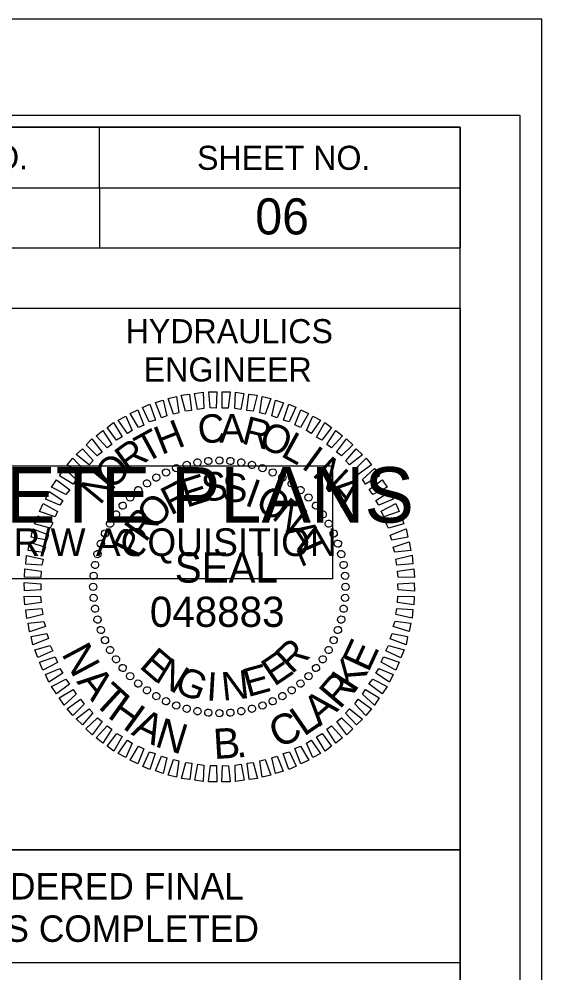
# Model space of a CAD drawing. Extents: x 1639431 to 1641888, y 841916 to 843940.
# Drawn here: x 1641779.1 to 1641887.8, y 842813.2 to 843011.3 of the extents above; entities that cross this region are included whole.
import ezdxf

# ---------------------------------------------------------------- set-up
doc = ezdxf.new("R2010")
doc.units = 0
for name, color, linetype in [('Default', 7, 'Continuous'), ('Old_Level_2', 7, 'Continuous'), ('Sheet Data Field CELL', 7, 'Continuous'), ('Sheet Plan CELL', 7, 'Continuous'), ('Sheet Plot Border Inside CELL', 7, 'Continuous'), ('Sheet Plot Border Outside CELL', 7, 'Continuous'), ('Sheet Sticker Exception Certification CELL', 7, 'Continuous'), ('Sheet Sticker Incomplete CELL', 7, 'Continuous')]:
    doc.layers.add(name, color=color, linetype=linetype)

msp = doc.modelspace()

# ---------------------------------------------------------------- linework, layer by layer
at = {"layer": 'Old_Level_2'}
for p, q in [((1641813.93, 842918.72), (1641813.93, 842918.72)), ((1641816.22, 842919.18), (1641816.22, 842919.18)), ((1641818.46, 842919.53), (1641818.46, 842919.53)), ((1641820.76, 842919.62), (1641820.76, 842919.62)), ((1641823.07, 842919.51), (1641823.07, 842919.51)), ((1641825.32, 842919.18), (1641825.32, 842919.18)), ((1641827.52, 842918.75), (1641827.52, 842918.75)), ((1641809.67, 842917.18), (1641809.67, 842917.18)), ((1641811.74, 842918.05), (1641811.74, 842918.05)), ((1641829.73, 842918.05), (1641829.73, 842918.05)), ((1641831.84, 842917.15), (1641831.84, 842917.15)), ((1641805.68, 842914.86), (1641805.68, 842914.86)), ((1641807.65, 842916.1), (1641807.65, 842916.1)), ((1641833.9, 842916.14), (1641833.9, 842916.14)), ((1641835.8, 842914.87), (1641835.8, 842914.87)), ((1641803.87, 842913.52), (1641803.87, 842913.52)), ((1641837.66, 842913.49), (1641837.66, 842913.49)), ((1641800.64, 842910.28), (1641800.64, 842910.28)), ((1641802.18, 842911.92), (1641802.18, 842911.92)), ((1641839.31, 842911.95), (1641839.31, 842911.95)), ((1641840.9, 842910.25), (1641840.9, 842910.25)), ((1641799.26, 842908.42), (1641799.26, 842908.42)), ((1641842.24, 842908.44), (1641842.24, 842908.44)), ((1641797.98, 842906.52), (1641797.98, 842906.52)), ((1641843.48, 842906.47), (1641843.48, 842906.47)), ((1641796.97, 842904.46), (1641796.97, 842904.46)), ((1641844.56, 842904.45), (1641844.56, 842904.45)), ((1641796.07, 842902.35), (1641796.07, 842902.35)), ((1641845.43, 842902.38), (1641845.43, 842902.38)), ((1641795.37, 842900.14), (1641795.37, 842900.14)), ((1641846.1, 842900.19), (1641846.1, 842900.19)), ((1641794.94, 842897.94), (1641794.94, 842897.94)), ((1641846.56, 842897.9), (1641846.56, 842897.9)), ((1641794.61, 842895.69), (1641794.61, 842895.69)), ((1641846.91, 842895.66), (1641846.91, 842895.66)), ((1641794.5, 842893.38), (1641794.5, 842893.38)), ((1641820.75, 842893.37), (1641820.75, 842893.37)), ((1641847, 842893.36), (1641847, 842893.36)), ((1641794.59, 842891.08), (1641794.59, 842891.08)), ((1641846.89, 842891.05), (1641846.89, 842891.05)), ((1641794.94, 842888.84), (1641794.94, 842888.84)), ((1641846.56, 842888.8), (1641846.56, 842888.8)), ((1641795.4, 842886.55), (1641795.4, 842886.55)), ((1641846.13, 842886.6), (1641846.13, 842886.6)), ((1641796.07, 842884.36), (1641796.07, 842884.36)), ((1641845.43, 842884.39), (1641845.43, 842884.39)), ((1641796.94, 842882.29), (1641796.94, 842882.29)), ((1641844.53, 842882.28), (1641844.53, 842882.28)), ((1641798.02, 842880.27), (1641798.02, 842880.27)), ((1641843.52, 842880.22), (1641843.52, 842880.22)), ((1641799.26, 842878.3), (1641799.26, 842878.3)), ((1641842.25, 842878.32), (1641842.25, 842878.32)), ((1641800.6, 842876.49), (1641800.6, 842876.49)), ((1641802.2, 842874.79), (1641802.2, 842874.79)), ((1641839.33, 842874.82), (1641839.33, 842874.82)), ((1641840.87, 842876.46), (1641840.87, 842876.46)), ((1641803.84, 842873.25), (1641803.84, 842873.25)), ((1641837.63, 842873.22), (1641837.63, 842873.22)), ((1641805.7, 842871.87), (1641805.7, 842871.87)), ((1641807.6, 842870.6), (1641807.6, 842870.6)), ((1641833.86, 842870.64), (1641833.86, 842870.64)), ((1641835.82, 842871.88), (1641835.82, 842871.88)), ((1641809.66, 842869.59), (1641809.66, 842869.59)), ((1641811.77, 842868.69), (1641811.77, 842868.69)), ((1641829.76, 842868.69), (1641829.76, 842868.69)), ((1641831.83, 842869.56), (1641831.83, 842869.56)), ((1641813.98, 842867.99), (1641813.98, 842867.99)), ((1641816.18, 842867.56), (1641816.18, 842867.56)), ((1641818.44, 842867.23), (1641818.44, 842867.23)), ((1641820.74, 842867.12), (1641820.74, 842867.12)), ((1641823.04, 842867.21), (1641823.04, 842867.21)), ((1641825.28, 842867.56), (1641825.28, 842867.56)), ((1641827.57, 842868.02), (1641827.57, 842868.02))]:
    msp.add_line(p, q, dxfattribs=at)
for points in [[(1641808.74, 842928.51), (1641807.48, 842931.63), (1641809.09, 842932.13), (1641809.83, 842928.9)], [(1641811.23, 842929.24), (1641810.08, 842932.51), (1641811.85, 842932.91), (1641812.33, 842929.52)], [(1641813.73, 842929.85), (1641812.84, 842933.19), (1641814.56, 842933.37), (1641814.99, 842930.03)], [(1641816.24, 842930.21), (1641815.6, 842933.55), (1641817.38, 842933.79), (1641817.49, 842930.39)], [(1641818.85, 842930.52), (1641818.53, 842933.91), (1641820.25, 842933.89), (1641820.1, 842930.49)], [(1641821.36, 842930.51), (1641821.3, 842933.91), (1641823.02, 842933.89), (1641822.61, 842930.48)], [(1641823.97, 842930.4), (1641824.12, 842933.8), (1641825.85, 842933.52), (1641825.23, 842930.21)], [(1641826.49, 842930.03), (1641826.9, 842933.38), (1641828.63, 842933.15), (1641827.75, 842929.89)], [(1641829.17, 842929.5), (1641829.63, 842932.9), (1641831.42, 842932.52), (1641830.27, 842929.25)], [(1641831.69, 842928.86), (1641832.42, 842932.12), (1641834.05, 842931.62), (1641832.79, 842928.51)], [(1641803.91, 842926.49), (1641802.18, 842929.39), (1641803.79, 842930.15), (1641805.05, 842926.98)], [(1641806.19, 842927.63), (1641804.78, 842930.64), (1641806.33, 842931.29), (1641807.49, 842927.97)], [(1641834.06, 842927.96), (1641835.2, 842931.28), (1641836.68, 842930.67), (1641835.27, 842927.62)], [(1641836.43, 842927.01), (1641837.68, 842930.12), (1641839.31, 842929.41), (1641837.59, 842926.45)], [(1641801.68, 842925.2), (1641799.7, 842927.99), (1641801.3, 842928.85), (1641802.66, 842925.84)], [(1641838.85, 842925.85), (1641840.21, 842928.85), (1641841.8, 842927.99), (1641839.86, 842925.24)], [(1641799.4, 842923.85), (1641797.42, 842926.48), (1641798.77, 842927.5), (1641800.54, 842924.5)], [(1641840.92, 842924.47), (1641842.69, 842927.54), (1641844.07, 842926.46), (1641842.08, 842923.86)], [(1641795.38, 842920.59), (1641793.04, 842922.85), (1641794.27, 842924.13), (1641796.36, 842921.34)], [(1641797.45, 842922.25), (1641795.15, 842924.72), (1641796.55, 842925.84), (1641798.43, 842922.95)], [(1641843.09, 842922.94), (1641844.97, 842925.85), (1641846.35, 842924.72), (1641844.09, 842922.23)], [(1641845.1, 842921.36), (1641847.2, 842924.11), (1641848.48, 842922.88), (1641846.11, 842920.59)], [(1641793.69, 842918.73), (1641790.99, 842920.83), (1641792.27, 842922.05), (1641794.51, 842919.58)], [(1641847.02, 842919.56), (1641849.22, 842922.05), (1641850.5, 842920.82), (1641847.82, 842918.74)], [(1641791.89, 842916.71), (1641789.14, 842918.7), (1641790.27, 842920.08), (1641792.61, 842917.67)], [(1641848.88, 842917.71), (1641851.24, 842920.1), (1641852.37, 842918.71), (1641849.63, 842916.68)], [(1641790.36, 842914.7), (1641787.51, 842916.43), (1641788.47, 842917.96), (1641791.02, 842915.7)], [(1641850.48, 842915.7), (1641853.01, 842917.94), (1641854.03, 842916.44), (1641851.13, 842914.71)], [(1641788.83, 842912.58), (1641785.87, 842914.1), (1641786.89, 842915.58), (1641789.65, 842913.54)], [(1641851.88, 842913.58), (1641854.62, 842915.61), (1641855.64, 842914.06), (1641852.63, 842912.54)], [(1641787.61, 842910.31), (1641784.61, 842911.57), (1641785.37, 842913.2), (1641788.22, 842911.32)], [(1641853.28, 842911.3), (1641856.18, 842913.18), (1641856.88, 842911.57), (1641853.92, 842910.32)], [(1641786.61, 842907.89), (1641783.35, 842909.03), (1641784.1, 842910.67), (1641787.11, 842909.05)], [(1641854.36, 842909.07), (1641857.42, 842910.69), (1641858.13, 842909.03), (1641854.91, 842907.93)], [(1641785.6, 842905.57), (1641782.35, 842906.45), (1641783, 842908.09), (1641786.16, 842906.68)], [(1641855.35, 842906.63), (1641858.51, 842908.04), (1641859.12, 842906.43), (1641855.89, 842905.54)], [(1641784.86, 842903.05), (1641781.61, 842903.67), (1641781.95, 842905.4), (1641785.26, 842904.15)], [(1641856.23, 842904.13), (1641859.55, 842905.4), (1641859.9, 842903.68), (1641856.61, 842903.04)], [(1641784.23, 842900.52), (1641780.98, 842900.89), (1641781.31, 842902.67), (1641784.63, 842901.63)], [(1641856.9, 842901.64), (1641860.18, 842902.69), (1641860.52, 842900.92), (1641857.23, 842900.54)], [(1641783.86, 842897.85), (1641780.5, 842898.11), (1641780.68, 842899.89), (1641784.1, 842899.11)], [(1641857.41, 842899.14), (1641860.8, 842899.93), (1641860.99, 842898.15), (1641857.65, 842897.88)], [(1641783.64, 842895.34), (1641780.24, 842895.38), (1641780.31, 842897.11), (1641783.72, 842896.59)], [(1641857.77, 842896.63), (1641861.16, 842897.11), (1641861.3, 842895.33), (1641857.9, 842895.38)], [(1641783.63, 842892.72), (1641780.24, 842892.51), (1641780.2, 842894.28), (1641783.61, 842893.98)], [(1641857.87, 842894.02), (1641861.27, 842894.23), (1641861.3, 842892.46), (1641857.89, 842892.76)], [(1641783.73, 842890.11), (1641780.34, 842889.63), (1641780.2, 842891.41), (1641783.6, 842891.36)], [(1641857.86, 842891.4), (1641861.26, 842891.36), (1641861.19, 842889.63), (1641857.78, 842890.15)], [(1641784.09, 842887.61), (1641780.7, 842886.81), (1641780.51, 842888.59), (1641783.86, 842888.86)], [(1641857.65, 842888.89), (1641861, 842888.63), (1641860.82, 842886.85), (1641857.41, 842887.63)], [(1641784.6, 842885.1), (1641781.32, 842884.05), (1641780.98, 842885.83), (1641784.27, 842886.2)], [(1641857.27, 842886.22), (1641860.52, 842885.85), (1641860.19, 842884.07), (1641856.87, 842885.11)], [(1641785.27, 842882.61), (1641781.95, 842881.34), (1641781.6, 842883.06), (1641784.89, 842883.7)], [(1641856.64, 842883.69), (1641859.89, 842883.07), (1641859.56, 842881.34), (1641856.24, 842882.59)], [(1641786.15, 842880.11), (1641782.99, 842878.7), (1641782.38, 842880.31), (1641785.61, 842881.2)], [(1641855.9, 842881.17), (1641859.16, 842880.29), (1641858.5, 842878.65), (1641855.34, 842880.06)], [(1641787.14, 842877.67), (1641784.08, 842876.05), (1641783.37, 842877.71), (1641786.59, 842878.81)], [(1641854.89, 842878.85), (1641858.15, 842877.71), (1641857.4, 842876.07), (1641854.39, 842877.69)], [(1641788.22, 842875.44), (1641785.33, 842873.56), (1641784.62, 842875.17), (1641787.58, 842876.42)], [(1641853.89, 842876.43), (1641856.89, 842875.17), (1641856.14, 842873.54), (1641853.28, 842875.42)], [(1641789.62, 842873.16), (1641786.88, 842871.13), (1641785.86, 842872.68), (1641788.87, 842874.2)], [(1641852.67, 842874.16), (1641855.63, 842872.64), (1641854.61, 842871.16), (1641851.85, 842873.2)], [(1641791.02, 842871.04), (1641788.49, 842868.8), (1641787.47, 842870.3), (1641790.37, 842872.03)], [(1641851.14, 842872.04), (1641854, 842870.31), (1641853.03, 842868.78), (1641850.48, 842871.04)], [(1641792.62, 842869.03), (1641790.26, 842866.64), (1641789.14, 842868.03), (1641791.87, 842870.06)], [(1641849.61, 842870.03), (1641852.36, 842868.04), (1641851.23, 842866.66), (1641848.89, 842869.07)], [(1641794.48, 842867.18), (1641792.28, 842864.69), (1641791, 842865.92), (1641793.69, 842868)], [(1641847.81, 842868.01), (1641850.52, 842865.91), (1641849.23, 842864.69), (1641846.99, 842867.16)], [(1641796.4, 842865.38), (1641794.3, 842862.63), (1641793.03, 842863.86), (1641795.39, 842866.15)], [(1641846.12, 842866.15), (1641848.46, 842863.89), (1641847.23, 842862.61), (1641845.14, 842865.4)], [(1641798.41, 842863.8), (1641796.53, 842860.89), (1641795.15, 842862.02), (1641797.41, 842864.51)], [(1641800.58, 842862.27), (1641798.81, 842859.2), (1641797.43, 842860.28), (1641799.42, 842862.88)], [(1641842.1, 842862.89), (1641844.08, 842860.26), (1641842.74, 842859.24), (1641840.96, 842862.24)], [(1641844.06, 842864.49), (1641846.35, 842862.02), (1641844.96, 842860.9), (1641843.07, 842863.79)], [(1641802.65, 842860.89), (1641801.29, 842857.89), (1641799.7, 842858.75), (1641801.64, 842861.5)], [(1641839.82, 842861.54), (1641841.8, 842858.75), (1641840.2, 842857.89), (1641838.84, 842860.9)], [(1641805.07, 842859.73), (1641803.82, 842856.62), (1641802.19, 842857.33), (1641803.91, 842860.29)], [(1641807.44, 842858.78), (1641806.3, 842855.46), (1641804.82, 842856.07), (1641806.23, 842859.12)], [(1641835.31, 842859.11), (1641836.72, 842856.1), (1641835.17, 842855.45), (1641834.01, 842858.77)], [(1641837.59, 842860.25), (1641839.32, 842857.35), (1641837.71, 842856.59), (1641836.45, 842859.76)], [(1641809.81, 842857.88), (1641809.08, 842854.62), (1641807.46, 842855.12), (1641808.71, 842858.23)], [(1641812.33, 842857.24), (1641811.87, 842853.84), (1641810.09, 842854.22), (1641811.23, 842857.49)], [(1641815.01, 842856.71), (1641814.6, 842853.36), (1641812.87, 842853.59), (1641813.75, 842856.85)], [(1641827.77, 842856.89), (1641828.66, 842853.55), (1641826.94, 842853.37), (1641826.52, 842856.71)], [(1641830.27, 842857.5), (1641831.42, 842854.23), (1641829.65, 842853.83), (1641829.17, 842857.22)], [(1641832.76, 842858.23), (1641834.02, 842855.11), (1641832.41, 842854.61), (1641831.67, 842857.84)], [(1641817.53, 842856.34), (1641817.38, 842852.94), (1641815.65, 842853.22), (1641816.27, 842856.53)], [(1641820.14, 842856.23), (1641820.2, 842852.83), (1641818.48, 842852.85), (1641818.89, 842856.26)], [(1641822.65, 842856.22), (1641822.97, 842852.83), (1641821.25, 842852.85), (1641821.4, 842856.25)], [(1641825.26, 842856.53), (1641825.9, 842853.19), (1641824.12, 842852.95), (1641824.01, 842856.35)]]:
    msp.add_lwpolyline(points, close=True, dxfattribs=at)
for centre, major_axis in [((1641818.46, 842919.5), (-0.066, 0.75)), ((1641820.75, 842919.6), (0, 0.753)), ((1641823.04, 842919.5), (0.066, 0.75)), ((1641811.78, 842918.02), (-0.258, 0.708)), ((1641813.96, 842918.7), (-0.195, 0.727)), ((1641816.2, 842919.2), (-0.131, 0.742)), ((1641825.3, 842919.2), (0.131, 0.742)), ((1641827.54, 842918.7), (0.195, 0.727)), ((1641829.72, 842918.02), (0.258, 0.708)), ((1641807.64, 842916.08), (-0.376, 0.652)), ((1641809.67, 842917.14), (-0.318, 0.682)), ((1641831.83, 842917.14), (0.318, 0.682)), ((1641833.86, 842916.08), (0.376, 0.652)), ((1641803.89, 842913.46), (-0.484, 0.577)), ((1641805.71, 842914.85), (-0.432, 0.617)), ((1641835.79, 842914.85), (0.432, 0.617)), ((1641837.61, 842913.46), (0.484, 0.577)), ((1641802.2, 842911.92), (-0.532, 0.532)), ((1641839.3, 842911.92), (0.532, 0.532)), ((1641800.66, 842910.23), (-0.577, 0.484)), ((1641840.84, 842910.23), (0.577, 0.484)), ((1641799.27, 842908.41), (-0.617, 0.432)), ((1641842.24, 842908.41), (0.617, 0.432)), ((1641798.04, 842906.48), (-0.652, 0.376)), ((1641843.46, 842906.48), (0.652, 0.376)), ((1641796.98, 842904.45), (-0.682, 0.318)), ((1641844.52, 842904.45), (0.682, 0.318)), ((1641796.1, 842902.34), (-0.708, 0.258)), ((1641845.4, 842902.34), (0.708, 0.258)), ((1641795.42, 842900.16), (-0.727, 0.195)), ((1641846.08, 842900.16), (0.727, 0.195)), ((1641794.92, 842897.92), (-0.742, 0.131)), ((1641846.58, 842897.92), (0.742, 0.131)), ((1641794.62, 842895.66), (-0.75, 0.066)), ((1641846.88, 842895.66), (0.75, 0.066)), ((1641794.52, 842893.37), (-0.753, 0)), ((1641846.98, 842893.37), (0.753, 0)), ((1641794.62, 842891.08), (-0.75, -0.066)), ((1641846.88, 842891.08), (0.75, -0.066)), ((1641794.92, 842888.82), (-0.742, -0.131)), ((1641846.58, 842888.82), (0.742, -0.131)), ((1641795.42, 842886.58), (-0.727, -0.195)), ((1641846.08, 842886.58), (0.727, -0.195)), ((1641796.1, 842884.4), (-0.708, -0.258)), ((1641845.4, 842884.4), (0.708, -0.258)), ((1641796.98, 842882.29), (-0.682, -0.318)), ((1641844.52, 842882.29), (0.682, -0.318)), ((1641798.04, 842880.26), (-0.652, -0.376)), ((1641843.46, 842880.26), (0.652, -0.376)), ((1641799.27, 842878.33), (-0.617, -0.432)), ((1641842.24, 842878.33), (0.617, -0.432)), ((1641800.66, 842876.51), (-0.577, -0.484)), ((1641840.84, 842876.51), (0.577, -0.484)), ((1641802.2, 842874.82), (-0.532, -0.532)), ((1641839.3, 842874.82), (0.532, -0.532)), ((1641803.89, 842873.28), (-0.484, -0.577)), ((1641805.71, 842871.89), (-0.432, -0.617)), ((1641835.79, 842871.89), (0.432, -0.617)), ((1641837.61, 842873.28), (0.484, -0.577)), ((1641807.64, 842870.66), (-0.376, -0.652)), ((1641833.86, 842870.66), (0.376, -0.652)), ((1641809.67, 842869.6), (-0.318, -0.682)), ((1641811.78, 842868.72), (-0.258, -0.708)), ((1641813.96, 842868.04), (-0.195, -0.727)), ((1641827.54, 842868.04), (0.195, -0.727)), ((1641829.72, 842868.72), (0.258, -0.708)), ((1641831.83, 842869.6), (0.318, -0.682)), ((1641816.2, 842867.54), (-0.131, -0.742)), ((1641818.46, 842867.24), (-0.066, -0.75)), ((1641820.75, 842867.14), (0, -0.753)), ((1641823.04, 842867.24), (0.066, -0.75)), ((1641825.3, 842867.54), (0.131, -0.742))]:
    msp.add_ellipse(centre, major_axis=major_axis, ratio=0.999708, dxfattribs=at)
at = {"layer": 'Sheet Plan CELL'}
for p, q in [((1641795.76, 842988.76), (1641795.81, 842963.76)), ((1641670.74, 842976.28), (1641870.79, 842976.27)), ((1641670.75, 842963.74), (1641870.79, 842963.77)), ((1641670.75, 842963.74), (1641870.79, 842963.77))]:
    msp.add_line(p, q, dxfattribs=at)
for points in [[(1640370.79, 841938.82), (1640370.76, 842988.79), (1641670.75, 842988.83), (1641670.76, 842838.77), (1641870.8, 842838.76), (1641870.8, 841938.82)], [(1641870.83, 842988.82), (1640370.79, 842988.82), (1640370.79, 841938.82), (1641870.8, 841938.82)], [(1641670.75, 842988.83), (1641870.83, 842988.82), (1641870.79, 842963.77), (1641670.75, 842963.74)], [(1641770.8, 842951.26), (1641870.79, 842951.27), (1641870.8, 842838.76), (1641770.8, 842838.74)]]:
    msp.add_lwpolyline(points, close=True, dxfattribs=at)
at = {"layer": 'Sheet Plot Border Inside CELL'}
msp.add_lwpolyline([(1640217.3, 841936.31), (1641883.29, 841936.32), (1641883.3, 842991.31), (1640217.3, 842991.31)], close=True, dxfattribs=at)
at = {"layer": 'Sheet Plot Border Outside CELL'}
msp.add_lwpolyline([(1640204.3, 841916.31), (1641887.8, 841916.31), (1641887.8, 843011.31), (1640204.3, 843011.31)], close=True, dxfattribs=at)
msp.add_lwpolyline([(1640204.3, 841916.31), (1641887.8, 841916.31), (1641887.8, 843011.31), (1640204.3, 843011.31)], close=True, dxfattribs=at)
at = {"layer": 'Sheet Sticker Exception Certification CELL'}
for p, q in [((1641670.76, 842838.77), (1641870.8, 842838.77)), ((1641670.76, 842838.77), (1641870.8, 842838.77)), ((1641870.8, 842838.76), (1641870.8, 842815.26)), ((1641870.8, 842838.76), (1641870.8, 842815.26)), ((1641870.8, 842815.27), (1641670.76, 842815.27)), ((1641870.8, 842815.27), (1641670.76, 842815.27))]:
    msp.add_line(p, q, dxfattribs=at)
at = {"layer": 'Sheet Sticker Incomplete CELL'}
msp.add_lwpolyline([(1641697.3, 842895.01), (1641697.3, 842918.51), (1641844.3, 842918.51), (1641844.3, 842895.01)], close=True, dxfattribs=at)

# ---------------------------------------------------------------- texts
at = {"layer": 'Default'}
for s, rotation, p in [('E', 65.2198, (1641851.72, 842875.41)), ('N', 298.0773, (1641787.83, 842879.48)), ('K', 57.024, (1641848.85, 842871.18)), ('A', 308.6891, (1641790.94, 842873.64)), ('R', 49.6233, (1641845.77, 842867.75)), ('T', 317.4354, (1641794.28, 842869.34)), ('H', 324.1633, (1641797.27, 842866.4)), ('A', 40.877, (1641841.59, 842864.25)), ('A', 334.0411, (1641802.24, 842862.76)), ('C', 25.1886, (1641832.95, 842859.71)), ('L', 34.6689, (1641838.32, 842862.17)), ('N', 342.7874, (1641807.1, 842860.3)), ('B', 3.4911, (1641819.66, 842857.59)), ('.', 11.1059, (1641824.41, 842857.76))]:
    msp.add_text(s, height=6.27, rotation=rotation, dxfattribs=at).set_placement(p)
at = {"layer": 'Old_Level_2'}
for s, rotation, p in [('H', 21.6195, (1641808.72, 842920.72)), ('C', 7.2199, (1641816.63, 842922.95)), ('A', 0.0203, (1641820.75, 842923.34)), ('R', 345.6211, (1641825.15, 842923.2)), ('T', 28.8198, (1641805.35, 842918.94)), ('O', 338.4212, (1641828.66, 842922.48)), ('L', 331.2209, (1641833.3, 842920.63)), ('R', 36.0205, (1641801.83, 842916.57)), ('I', 324.0201, (1641837.58, 842918.19)), ('O', 43.2217, (1641798.28, 842913.27)), ('N', 316.8189, (1641839.85, 842916.61)), ('N', 50.4235, (1641795.93, 842910.19)), ('E', 17.6111, (1641813.93, 842909.78)), ('S', 8.2556, (1641817.52, 842910.94)), ('S', 358.9004, (1641821.28, 842911.06)), ('F', 26.967, (1641810.61, 842908.15)), ('I', 340.1896, (1641825.79, 842910.4)), ('A', 309.6172, (1641842.99, 842913.58)), ('O', 45.6812, (1641807.21, 842905)), ('O', 330.8335, (1641827.89, 842909.71)), ('N', 321.4766, (1641831.43, 842907.68)), ('R', 55.0397, (1641805.43, 842902.41)), ('A', 302.7603, (1641834.46, 842905.01)), ('P', 64.3989, (1641803.81, 842899.04)), ('L', 293.4009, (1641836.56, 842901.44)), ('E', 319.2769, (1641803.89, 842876.71)), ('R', 43.4814, (1641835.82, 842875.07)), ('N', 328.634, (1641807.07, 842873.94)), ('E', 34.1241, (1641832.15, 842872.55)), ('E', 15.4118, (1641826.64, 842870.41)), ('G', 337.9902, (1641811.09, 842871.66)), ('I', 356.7012, (1641817.97, 842869.79)), ('N', 6.0564, (1641821.48, 842869.69))]:
    msp.add_text(s, height=5.9, rotation=rotation, dxfattribs=at).set_placement(p)
for s, height, p in [('SEAL', 6.273, (1641811.48, 842894.25)), ('048883', 6.275, (1641806.3, 842885.05))]:
    msp.add_text(s, height=height, dxfattribs=at).set_placement(p)
at = {"layer": 'Sheet Data Field CELL'}
msp.add_text('06', height=7.5, rotation=0, dxfattribs=at).set_placement((1641828.22, 842966.57))
at = {"layer": 'Sheet Plan CELL'}
for s, height, p in [('PROJECT REFERENCE NO.', 5.0001, (1641692.95, 842980.11)), ('SHEET NO.', 5, (1641816.11, 842979.99)), ('HYDRAULICS', 5, (1641801.26, 842943.98)), ('ENGINEER', 5, (1641805.03, 842936.02))]:
    msp.add_text(s, height=height, rotation=0, dxfattribs=at).set_placement(p)
at = {"layer": 'Sheet Sticker Exception Certification CELL'}
for s, p in [('DOCUMENT NOT CONSIDERED FINAL', (1641691.83, 842828.42)), ('DOCUMENT NOT CONSIDERED FINAL', (1641691.83, 842828.42)), ('UNLESS ALL SIGNATURES COMPLETED', (1641686.76, 842819.62)), ('UNLESS ALL SIGNATURES COMPLETED', (1641686.76, 842819.62))]:
    msp.add_text(s, height=5.5, rotation=360, dxfattribs=at).set_placement(p)
at = {"layer": 'Sheet Sticker Incomplete CELL'}
for s, height, p in [('INCOMPLETE PLANS', 11.52, (1641706.25, 842906.71)), ('DO NOT USE FOR R/W ACQUISITION', 5.76, (1641709.5, 842899.76))]:
    msp.add_text(s, height=height, rotation=360, dxfattribs=at).set_placement(p)

doc.saveas('drawing.dxf')
